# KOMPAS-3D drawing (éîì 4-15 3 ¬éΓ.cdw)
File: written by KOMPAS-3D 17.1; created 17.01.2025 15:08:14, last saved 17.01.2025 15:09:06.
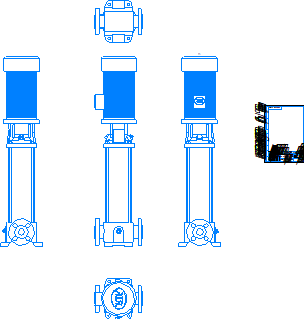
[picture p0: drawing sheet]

Sheet 1: A4, portrait

Title block, sheet 1: name: ВМН 4-15 3 кВт; designation: ВМН 4-15 3 кВт; material: Сталь 10  ГОСТ 1050-2013; mass: 138,66; sheets: 1; sheet format: A4; stored path: \\adlc.lan\data\АДЛ_ПКД\3D-модели\ADL production\Насосы ГРАНПАМП\Насосы ВМН\ВМН4\KOMPAS 3D\ВМН 4-15 3 кВт.cdw

Views: Вид 1, Спереди, Проекционный вид 2, Проекционный вид 3, Проекционный вид 4, Проекционный вид 5
Referenced files in \\adlc.lan\data\АДЛ_ПКД\3D-модели\ADL production\Насосы ГРАНПАМП\Насосы ВМН\ВМН4\KOMPAS 3D\: ВМН 4-15 3 кВт.m3d
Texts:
  Andrey
  АДЛ
Dimensions and other numbers on the sheet: 1:1; 1; 138,66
